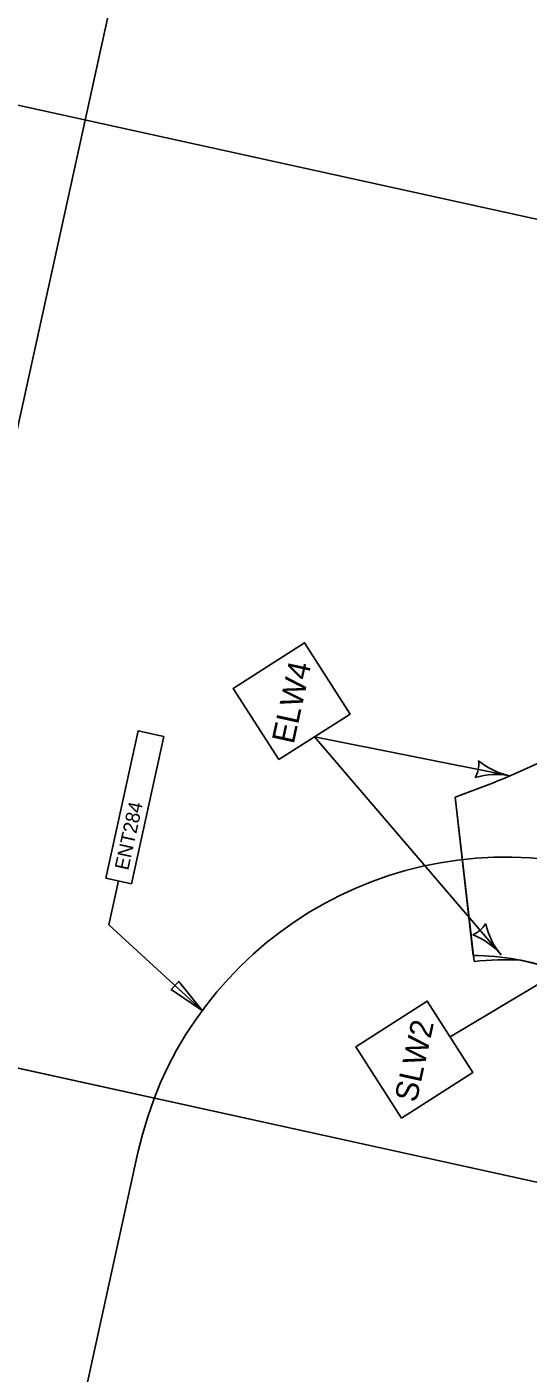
# Model space of a CAD drawing. Extents: x 14104283 to 14120882, y 8635219 to 8671666.
# Drawn here: x 14107697.2 to 14107857.1, y 8639738.3 to 8640167.7 of the extents above; entities that cross this region are included whole.
import ezdxf

# ---------------------------------------------------------------- set-up
doc = ezdxf.new("R2010")
doc.units = 0
for name, color, linetype in [('Alignment', 7, 'Continuous'), ('dsnNonPlotable', 7, 'Continuous'), ('dsnPaintPlaceEdgeLineRightWhite', 7, 'Continuous'), ('dsnShadingPaved', 7, 'Continuous'), ('dsnStdLabel', 7, 'Continuous'), ('dsnStgShadingPrevPav', 7, 'Continuous'), ('Text', 7, 'Continuous')]:
    doc.layers.add(name, color=color, linetype=linetype)

msp = doc.modelspace()

# ---------------------------------------------------------------- linework, layer by layer
at = {"layer": 'Alignment'}
msp.add_line((14107732.61, 8639808.61), (14107547.95, 8638968.47), dxfattribs=at)
msp.add_arc((14107849.81, 8639782.85), 120, 80.5511, 167.6032, dxfattribs=at)
at = {"layer": 'dsnNonPlotable'}
for points in [[(14107490.45, 8639880.3), (14107826.84, 8641411.28), (14108813.31, 8641194.53), (14108476.92, 8639663.55)], [(14107651.31, 8639844.94), (14107987.7, 8641375.92), (14108480.93, 8641267.54), (14108144.54, 8639736.56)], [(14107218.44, 8638642.33), (14107554.83, 8640173.31), (14108541.3, 8639956.56), (14108204.91, 8638425.58)]]:
    msp.add_lwpolyline(points, close=True, dxfattribs=at)
at = {"layer": 'dsnPaintPlaceEdgeLineRightWhite'}
for centre, radius, start, end in [((14107752.7, 8640158.5), 250, 288.9195, 302.3186), ((14107838.11, 8639781.51), 90, 80.198, 89.1076), ((14107844.07, 8639816), 55, 29.809, 80.198)]:
    msp.add_arc(centre, radius, start, end, dxfattribs=at)
at = {"layer": 'dsnShadingPaved'}
msp.add_line((14107839.51, 8639871.5), (14107833.76, 8639922), dxfattribs=at)
for centre, radius, start, end in [((14107752.7, 8640158.5), 250, 288.9195, 302.3186), ((14107838.11, 8639781.51), 90, 80.198, 89.1076), ((14107844.07, 8639816), 55, 29.809, 80.198)]:
    msp.add_arc(centre, radius, start, end, dxfattribs=at)
at = {"layer": 'dsnStdLabel'}
for p, q in [((14107788.92, 8639941.21), (14107848.5, 8639871.66)), ((14107788.92, 8639941.21), (14107851.33, 8639928.77)), ((14107832.18, 8639845.53), (14107894.21, 8639882.61))]:
    msp.add_line(p, q, dxfattribs=at)
for points in [[(14107777.54, 8639933.93), (14107800.29, 8639948.48), (14107785.74, 8639971.22), (14107762.99, 8639956.67)], [(14107816.71, 8639819.61), (14107839.45, 8639834.16), (14107824.9, 8639856.9), (14107802.16, 8639842.35)]]:
    msp.add_lwpolyline(points, close=True, dxfattribs=at)
for centre, radius, start, end in [((14107832.46, 8639932.53), 8.86, 330.9987, 6.4671), ((14107855.81, 8639951.28), 22.95, 230.6617, 258.733), ((14107846.84, 8639906.26), 22.95, 78.7328, 106.8041), ((14107835.98, 8639886.27), 8.86, 292.8571, 328.3255), ((14107865.93, 8639886.59), 22.95, 192.5201, 220.5914), ((14107831.08, 8639856.73), 22.95, 40.5913, 68.6625)]:
    msp.add_arc(centre, radius, start, end, dxfattribs=at)
at = {"layer": 'dsnStgShadingPrevPav'}
msp.add_line((14107833.76, 8639922), (14107839.82, 8639869.51), dxfattribs=at)
for centre, radius, start, end in [((14098576.76, 8641447.78), 9456, 348.449343, 351.672846), ((14098576.76, 8641447.78), 9468, 347.807255, 351.672846), ((14098576.76, 8641447.78), 9468, 348.194582, 351.672846), ((14107752.7, 8640158.5), 250, 288.9195, 302.3186), ((14107849.81, 8639782.85), 87.24, 86.7296, 96.5795), ((14107844.07, 8639816), 55, 23.1027, 78.7566), ((14098576.76, 8641447.78), 9450, 348.220778, 350.242299), ((14098576.76, 8641447.78), 9456, 348.449343, 350.195701)]:
    msp.add_arc(centre, radius, start, end, dxfattribs=at)
at = {"layer": 'Text'}
for points in [[(14107722.32, 8639896.13), (14107732.65, 8639943.12), (14107740.85, 8639941.31), (14107730.53, 8639894.33)], [(14107722.32, 8639896.13), (14107732.65, 8639943.12), (14107740.85, 8639941.31), (14107730.53, 8639894.33)], [(14107753.13, 8639853.93), (14107743.23, 8639860.6), (14107745.62, 8639863.21)]]:
    msp.add_lwpolyline(points, close=True, dxfattribs=at)
msp.add_lwpolyline([(14107726.42, 8639895.23), (14107723.27, 8639881.28), (14107753.13, 8639853.93)], dxfattribs=at)

# ---------------------------------------------------------------- texts
at = {"layer": 'dsnStdLabel'}
for s, p in [('ELW4', (14107782.27, 8639938.67)), ('SLW2', (14107821.44, 8639824.37))]:
    msp.add_text(s, height=7.2, rotation=77.6078, dxfattribs=at).set_placement(p)
at = {"layer": 'Text'}
msp.add_text('ENT284', height=4.484, rotation=77.6078, dxfattribs=at).set_placement((14107729.49, 8639898.43))

doc.saveas('drawing.dxf')
